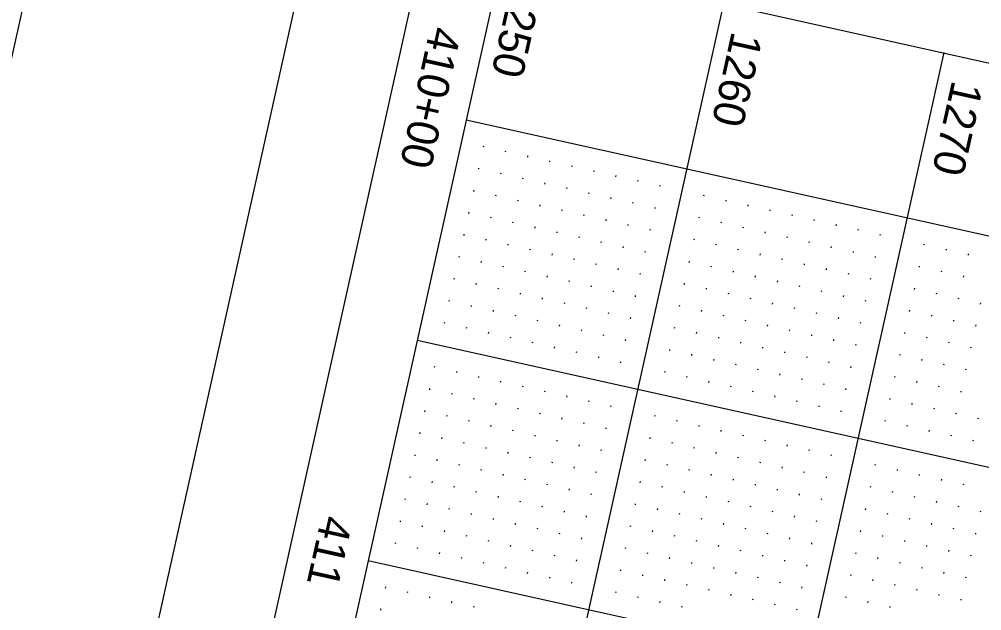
# Model space of a CAD drawing. Extents: x 2149268 to 2150830, y 142155 to 144285.
# Drawn here: x 2149611.6 to 2149824.8, y 143829.9 to 143960.9 of the extents above; entities that cross this region are included whole.
import ezdxf

# ---------------------------------------------------------------- set-up
doc = ezdxf.new("R2010")
doc.units = 0
for name, color, linetype in [('SHT_Plan_Profile_Sheet_Elev_Txt', 7, 'Continuous'), ('SHT_Plan_Profile_Sheet_Sta_Txt', 7, 'Continuous'), ('SHT_Plot_Shape_Full', 7, 'Continuous'), ('SHT_Plot_Shape_Half', 7, 'Continuous'), ('SHT_Profile_Grid_Major', 7, 'Continuous'), ('SHT_Profile_Grid_Minor', 7, 'Continuous'), ('SHT_Sheet_Border', 7, 'Continuous')]:
    doc.layers.add(name, color=color, linetype=linetype)

msp = doc.modelspace()

# ---------------------------------------------------------------- linework, layer by layer
at = {"layer": 'SHT_Plot_Shape_Full'}
msp.add_lwpolyline([(2150830.28, 143911.83), (2150439.58, 142154.75), (2149268.19, 142415.21), (2149658.89, 144172.3)], close=True, dxfattribs=at)
at = {"layer": 'SHT_Plot_Shape_Half'}
msp.add_lwpolyline([(2150772.24, 143840.86), (2150403.25, 142181.39), (2149329.47, 142420.15), (2149698.47, 144079.62)], close=True, dxfattribs=at)
at = {"layer": 'SHT_Profile_Grid_Major'}
for p, q in [((2149767.6, 143964.37), (2149425.74, 142426.92)), ((2149816.41, 143953.52), (2149474.54, 142416.07)), ((2149699.8, 143889.81), (2150187.88, 143781.28)), ((2149688.94, 143841), (2150177.02, 143732.47))]:
    msp.add_line(p, q, dxfattribs=at)
at = {"layer": 'SHT_Profile_Grid_Minor'}
for p, q in [((2149714.47, 143932.77), (2149714.42, 143932.53)), ((2149719.35, 143931.69), (2149719.3, 143931.44)), ((2149724.23, 143930.6), (2149724.18, 143930.36)), ((2149729.12, 143929.52), (2149729.06, 143929.27)), ((2149713.39, 143927.89), (2149713.33, 143927.65)), ((2149718.27, 143926.81), (2149718.21, 143926.56)), ((2149734, 143928.43), (2149733.94, 143928.19)), ((2149738.88, 143927.35), (2149738.82, 143927.1)), ((2149723.15, 143925.72), (2149723.1, 143925.48)), ((2149728.03, 143924.64), (2149727.98, 143924.39)), ((2149743.76, 143926.26), (2149743.7, 143926.02)), ((2149748.64, 143925.18), (2149748.58, 143924.93)), ((2149712.3, 143923.01), (2149712.25, 143922.77)), ((2149732.91, 143923.55), (2149732.86, 143923.31)), ((2149737.79, 143922.47), (2149737.74, 143922.22)), ((2149753.52, 143924.09), (2149753.47, 143923.85)), ((2149717.18, 143921.93), (2149717.13, 143921.68)), ((2149722.06, 143920.84), (2149722.01, 143920.6)), ((2149742.67, 143921.38), (2149742.62, 143921.14)), ((2149747.55, 143920.3), (2149747.5, 143920.05)), ((2149763.28, 143921.92), (2149763.23, 143921.68)), ((2149768.16, 143920.84), (2149768.11, 143920.59)), ((2149711.22, 143918.13), (2149711.16, 143917.89)), ((2149726.95, 143919.76), (2149726.89, 143919.51)), ((2149731.83, 143918.67), (2149731.77, 143918.43)), ((2149752.43, 143919.21), (2149752.38, 143918.97)), ((2149773.04, 143919.75), (2149772.99, 143919.51)), ((2149777.92, 143918.66), (2149777.87, 143918.42)), ((2149716.1, 143917.05), (2149716.04, 143916.8)), ((2149720.98, 143915.96), (2149720.92, 143915.72)), ((2149736.71, 143917.59), (2149736.65, 143917.34)), ((2149741.59, 143916.5), (2149741.53, 143916.26)), ((2149762.2, 143917.04), (2149762.14, 143916.8)), ((2149767.08, 143915.95), (2149767.02, 143915.71)), ((2149782.8, 143917.58), (2149782.75, 143917.34)), ((2149787.69, 143916.49), (2149787.63, 143916.25)), ((2149725.86, 143914.88), (2149725.81, 143914.63)), ((2149730.74, 143913.79), (2149730.69, 143913.55)), ((2149746.47, 143915.41), (2149746.41, 143915.17)), ((2149751.35, 143914.33), (2149751.29, 143914.09)), ((2149771.96, 143914.87), (2149771.9, 143914.63)), ((2149776.84, 143913.78), (2149776.78, 143913.54)), ((2149792.57, 143915.41), (2149792.51, 143915.16)), ((2149797.45, 143914.32), (2149797.39, 143914.08)), ((2149710.13, 143913.25), (2149710.08, 143913.01)), ((2149715.01, 143912.17), (2149714.96, 143911.92)), ((2149735.62, 143912.7), (2149735.57, 143912.46)), ((2149740.5, 143911.62), (2149740.45, 143911.38)), ((2149761.11, 143912.16), (2149761.06, 143911.92)), ((2149781.72, 143912.7), (2149781.66, 143912.45)), ((2149786.6, 143911.61), (2149786.55, 143911.37)), ((2149802.33, 143913.24), (2149802.27, 143912.99)), ((2149719.89, 143911.08), (2149719.84, 143910.84)), ((2149724.77, 143909.99), (2149724.72, 143909.75)), ((2149745.38, 143910.53), (2149745.33, 143910.29)), ((2149750.26, 143909.45), (2149750.21, 143909.2)), ((2149765.99, 143911.07), (2149765.94, 143910.83)), ((2149770.87, 143909.99), (2149770.82, 143909.74)), ((2149791.48, 143910.53), (2149791.43, 143910.28)), ((2149812.09, 143911.07), (2149812.03, 143910.82)), ((2149816.97, 143909.98), (2149816.92, 143909.74)), ((2149709.05, 143908.37), (2149708.99, 143908.13)), ((2149729.66, 143908.91), (2149729.6, 143908.67)), ((2149734.54, 143907.82), (2149734.48, 143907.58)), ((2149775.75, 143908.9), (2149775.7, 143908.66)), ((2149780.63, 143907.82), (2149780.58, 143907.57)), ((2149796.36, 143909.44), (2149796.31, 143909.2)), ((2149801.24, 143908.36), (2149801.19, 143908.11)), ((2149821.85, 143908.9), (2149821.8, 143908.65)), ((2149713.93, 143907.28), (2149713.87, 143907.04)), ((2149718.81, 143906.2), (2149718.75, 143905.95)), ((2149739.42, 143906.74), (2149739.36, 143906.49)), ((2149744.3, 143905.65), (2149744.24, 143905.41)), ((2149760.03, 143907.28), (2149759.97, 143907.03)), ((2149764.91, 143906.19), (2149764.85, 143905.95)), ((2149785.51, 143906.73), (2149785.46, 143906.49)), ((2149790.4, 143905.65), (2149790.34, 143905.4)), ((2149811, 143906.19), (2149810.95, 143905.94)), ((2149707.96, 143903.49), (2149707.91, 143903.24)), ((2149723.69, 143905.11), (2149723.63, 143904.87)), ((2149728.57, 143904.03), (2149728.52, 143903.78)), ((2149749.18, 143904.57), (2149749.12, 143904.32)), ((2149769.79, 143905.11), (2149769.73, 143904.86)), ((2149774.67, 143904.02), (2149774.61, 143903.78)), ((2149795.28, 143904.56), (2149795.22, 143904.32)), ((2149800.16, 143903.48), (2149800.1, 143903.23)), ((2149815.88, 143905.1), (2149815.83, 143904.86)), ((2149820.77, 143904.02), (2149820.71, 143903.77)), ((2149712.84, 143902.4), (2149712.79, 143902.16)), ((2149717.72, 143901.32), (2149717.67, 143901.07)), ((2149733.45, 143902.94), (2149733.4, 143902.7)), ((2149738.33, 143901.86), (2149738.28, 143901.61)), ((2149758.94, 143902.4), (2149758.89, 143902.15)), ((2149763.82, 143901.31), (2149763.77, 143901.07)), ((2149779.55, 143902.94), (2149779.49, 143902.69)), ((2149784.43, 143901.85), (2149784.38, 143901.61)), ((2149809.92, 143901.31), (2149809.86, 143901.06)), ((2149722.6, 143900.23), (2149722.55, 143899.99)), ((2149727.48, 143899.15), (2149727.43, 143898.9)), ((2149743.21, 143900.77), (2149743.16, 143900.53)), ((2149748.09, 143899.69), (2149748.04, 143899.44)), ((2149768.7, 143900.23), (2149768.65, 143899.98)), ((2149773.58, 143899.14), (2149773.53, 143898.9)), ((2149789.31, 143900.77), (2149789.26, 143900.52)), ((2149794.19, 143899.68), (2149794.14, 143899.44)), ((2149814.8, 143900.22), (2149814.75, 143899.98)), ((2149819.68, 143899.14), (2149819.63, 143898.89)), ((2149706.88, 143898.61), (2149706.82, 143898.36)), ((2149711.76, 143897.52), (2149711.7, 143897.28)), ((2149732.37, 143898.06), (2149732.31, 143897.82)), ((2149737.25, 143896.98), (2149737.19, 143896.73)), ((2149757.85, 143897.52), (2149757.8, 143897.27)), ((2149778.46, 143898.06), (2149778.41, 143897.81)), ((2149783.34, 143896.97), (2149783.29, 143896.73)), ((2149799.07, 143898.6), (2149799.02, 143898.35)), ((2149824.56, 143898.05), (2149824.51, 143897.81)), ((2149716.64, 143896.44), (2149716.58, 143896.19)), ((2149721.52, 143895.35), (2149721.46, 143895.11)), ((2149742.13, 143895.89), (2149742.07, 143895.65)), ((2149747.01, 143894.81), (2149746.95, 143894.56)), ((2149762.74, 143896.43), (2149762.68, 143896.19)), ((2149767.62, 143895.35), (2149767.56, 143895.1)), ((2149788.22, 143895.89), (2149788.17, 143895.64)), ((2149793.11, 143894.8), (2149793.05, 143894.56)), ((2149808.83, 143896.43), (2149808.78, 143896.18)), ((2149813.71, 143895.34), (2149813.66, 143895.1)), ((2149705.79, 143893.73), (2149705.74, 143893.48)), ((2149710.67, 143892.64), (2149710.62, 143892.4)), ((2149726.4, 143894.27), (2149726.35, 143894.02)), ((2149731.28, 143893.18), (2149731.23, 143892.94)), ((2149756.77, 143892.64), (2149756.72, 143892.39)), ((2149772.5, 143894.26), (2149772.44, 143894.02)), ((2149777.38, 143893.18), (2149777.32, 143892.93)), ((2149797.99, 143893.72), (2149797.93, 143893.47)), ((2149818.59, 143894.25), (2149818.54, 143894.01)), ((2149823.48, 143893.17), (2149823.42, 143892.93)), ((2149715.55, 143891.56), (2149715.5, 143891.31)), ((2149720.43, 143890.47), (2149720.38, 143890.23)), ((2149736.16, 143892.1), (2149736.11, 143891.85)), ((2149741.04, 143891.01), (2149740.99, 143890.77)), ((2149761.65, 143891.55), (2149761.6, 143891.31)), ((2149766.53, 143890.47), (2149766.48, 143890.22)), ((2149782.26, 143892.09), (2149782.2, 143891.85)), ((2149787.14, 143891.01), (2149787.09, 143890.76)), ((2149807.75, 143891.54), (2149807.69, 143891.3)), ((2149812.63, 143890.46), (2149812.57, 143890.22)), ((2149725.31, 143889.39), (2149725.26, 143889.14)), ((2149730.19, 143888.3), (2149730.14, 143888.06)), ((2149745.92, 143889.93), (2149745.87, 143889.68)), ((2149771.41, 143889.38), (2149771.36, 143889.14)), ((2149776.29, 143888.29), (2149776.24, 143888.05)), ((2149792.02, 143889.92), (2149791.97, 143889.68)), ((2149796.9, 143888.83), (2149796.85, 143888.59)), ((2149817.51, 143889.37), (2149817.46, 143889.13)), ((2149822.39, 143888.29), (2149822.34, 143888.04)), ((2149735.08, 143887.22), (2149735.02, 143886.97)), ((2149739.96, 143886.13), (2149739.9, 143885.89)), ((2149755.68, 143887.76), (2149755.63, 143887.51)), ((2149760.57, 143886.67), (2149760.51, 143886.43)), ((2149781.17, 143887.21), (2149781.12, 143886.97)), ((2149786.05, 143886.12), (2149786, 143885.88)), ((2149806.66, 143886.66), (2149806.61, 143886.42)), ((2149703.62, 143883.97), (2149703.57, 143883.72)), ((2149744.84, 143885.04), (2149744.78, 143884.8)), ((2149765.45, 143885.58), (2149765.39, 143885.34)), ((2149770.33, 143884.5), (2149770.27, 143884.26)), ((2149790.94, 143885.04), (2149790.88, 143884.79)), ((2149795.82, 143883.95), (2149795.76, 143883.71)), ((2149811.54, 143885.58), (2149811.49, 143885.33)), ((2149816.42, 143884.49), (2149816.37, 143884.25)), ((2149708.5, 143882.88), (2149708.45, 143882.64)), ((2149713.38, 143881.79), (2149713.33, 143881.55)), ((2149754.6, 143882.87), (2149754.54, 143882.63)), ((2149759.48, 143881.79), (2149759.43, 143881.55)), ((2149775.21, 143883.41), (2149775.15, 143883.17)), ((2149780.09, 143882.33), (2149780.03, 143882.08)), ((2149805.58, 143881.78), (2149805.52, 143881.54)), ((2149821.31, 143883.41), (2149821.25, 143883.16)), ((2149718.26, 143880.71), (2149718.21, 143880.47)), ((2149723.14, 143879.62), (2149723.09, 143879.38)), ((2149764.36, 143880.7), (2149764.31, 143880.46)), ((2149769.24, 143879.62), (2149769.19, 143879.37)), ((2149784.97, 143881.24), (2149784.91, 143881)), ((2149789.85, 143880.16), (2149789.8, 143879.91)), ((2149810.46, 143880.7), (2149810.4, 143880.45)), ((2149815.34, 143879.61), (2149815.28, 143879.37)), ((2149702.54, 143879.08), (2149702.48, 143878.84)), ((2149707.42, 143878), (2149707.36, 143877.76)), ((2149728.02, 143878.54), (2149727.97, 143878.3)), ((2149774.12, 143878.53), (2149774.07, 143878.29)), ((2149794.73, 143879.07), (2149794.68, 143878.83)), ((2149820.22, 143878.53), (2149820.17, 143878.28)), ((2149712.3, 143876.91), (2149712.24, 143876.67)), ((2149717.18, 143875.83), (2149717.12, 143875.58)), ((2149732.91, 143877.45), (2149732.85, 143877.21)), ((2149737.79, 143876.37), (2149737.73, 143876.12)), ((2149779, 143877.45), (2149778.95, 143877.2)), ((2149783.88, 143876.36), (2149783.83, 143876.12)), ((2149804.49, 143876.9), (2149804.44, 143876.66)), ((2149809.37, 143875.82), (2149809.32, 143875.57)), ((2149701.45, 143874.2), (2149701.4, 143873.96)), ((2149722.06, 143874.74), (2149722, 143874.5)), ((2149726.94, 143873.66), (2149726.88, 143873.41)), ((2149742.67, 143875.28), (2149742.61, 143875.04)), ((2149788.76, 143875.28), (2149788.71, 143875.03)), ((2149793.65, 143874.19), (2149793.59, 143873.95)), ((2149814.25, 143874.73), (2149814.2, 143874.49)), ((2149819.13, 143873.65), (2149819.08, 143873.4)), ((2149706.33, 143873.12), (2149706.28, 143872.87)), ((2149711.21, 143872.03), (2149711.16, 143871.79)), ((2149731.82, 143872.57), (2149731.77, 143872.33)), ((2149736.7, 143871.49), (2149736.65, 143871.24)), ((2149752.43, 143873.11), (2149752.37, 143872.87)), ((2149757.31, 143872.03), (2149757.25, 143871.78)), ((2149803.41, 143872.02), (2149803.35, 143871.78)), ((2149824.02, 143872.56), (2149823.96, 143872.32)), ((2149700.36, 143869.32), (2149700.31, 143869.08)), ((2149716.09, 143870.95), (2149716.04, 143870.7)), ((2149720.97, 143869.86), (2149720.92, 143869.62)), ((2149741.58, 143870.4), (2149741.53, 143870.16)), ((2149762.19, 143870.94), (2149762.14, 143870.7)), ((2149767.07, 143869.86), (2149767.02, 143869.61)), ((2149808.29, 143870.94), (2149808.23, 143870.69)), ((2149813.17, 143869.85), (2149813.11, 143869.61)), ((2149705.25, 143868.24), (2149705.19, 143867.99)), ((2149710.13, 143867.15), (2149710.07, 143866.91)), ((2149725.85, 143868.78), (2149725.8, 143868.53)), ((2149730.73, 143867.69), (2149730.68, 143867.45)), ((2149751.34, 143868.23), (2149751.29, 143867.99)), ((2149756.22, 143867.15), (2149756.17, 143866.9)), ((2149771.95, 143868.77), (2149771.9, 143868.53)), ((2149776.83, 143867.69), (2149776.78, 143867.44)), ((2149818.05, 143868.77), (2149818, 143868.52)), ((2149822.93, 143867.68), (2149822.88, 143867.44)), ((2149715.01, 143866.07), (2149714.95, 143865.82)), ((2149719.89, 143864.98), (2149719.83, 143864.74)), ((2149735.62, 143866.61), (2149735.56, 143866.36)), ((2149740.5, 143865.52), (2149740.44, 143865.28)), ((2149761.1, 143866.06), (2149761.05, 143865.82)), ((2149765.99, 143864.98), (2149765.93, 143864.73)), ((2149781.71, 143866.6), (2149781.66, 143866.36)), ((2149786.59, 143865.52), (2149786.54, 143865.27)), ((2149699.28, 143864.44), (2149699.23, 143864.2)), ((2149704.16, 143863.36), (2149704.11, 143863.11)), ((2149724.77, 143863.9), (2149724.71, 143863.65)), ((2149729.65, 143862.81), (2149729.6, 143862.57)), ((2149750.26, 143863.35), (2149750.2, 143863.11)), ((2149770.87, 143863.89), (2149770.81, 143863.65)), ((2149775.75, 143862.81), (2149775.69, 143862.56)), ((2149791.47, 143864.43), (2149791.42, 143864.19)), ((2149709.04, 143862.27), (2149708.99, 143862.03)), ((2149713.92, 143861.19), (2149713.87, 143860.94)), ((2149734.53, 143861.73), (2149734.48, 143861.48)), ((2149739.41, 143860.64), (2149739.36, 143860.4)), ((2149755.14, 143862.27), (2149755.08, 143862.02)), ((2149760.02, 143861.18), (2149759.97, 143860.94)), ((2149780.63, 143861.72), (2149780.57, 143861.48)), ((2149785.51, 143860.63), (2149785.45, 143860.39)), ((2149801.24, 143862.26), (2149801.18, 143862.02)), ((2149806.12, 143861.17), (2149806.06, 143860.93)), ((2149698.19, 143859.56), (2149698.14, 143859.32)), ((2149703.07, 143858.48), (2149703.02, 143858.23)), ((2149718.8, 143860.1), (2149718.75, 143859.86)), ((2149723.68, 143859.02), (2149723.63, 143858.77)), ((2149749.17, 143858.47), (2149749.12, 143858.23)), ((2149764.9, 143860.1), (2149764.85, 143859.85)), ((2149769.78, 143859.01), (2149769.73, 143858.77)), ((2149790.39, 143859.55), (2149790.34, 143859.31)), ((2149811, 143860.09), (2149810.94, 143859.85)), ((2149815.88, 143859), (2149815.82, 143858.76)), ((2149707.96, 143857.39), (2149707.9, 143857.15)), ((2149712.84, 143856.31), (2149712.78, 143856.06)), ((2149728.56, 143857.93), (2149728.51, 143857.69)), ((2149733.44, 143856.85), (2149733.39, 143856.6)), ((2149754.05, 143857.39), (2149754, 143857.14)), ((2149758.93, 143856.3), (2149758.88, 143856.06)), ((2149774.66, 143857.92), (2149774.61, 143857.68)), ((2149779.54, 143856.84), (2149779.49, 143856.6)), ((2149800.15, 143857.38), (2149800.1, 143857.14)), ((2149805.03, 143856.29), (2149804.98, 143856.05)), ((2149820.76, 143857.92), (2149820.71, 143857.67)), ((2149697.11, 143854.68), (2149697.05, 143854.44)), ((2149717.72, 143855.22), (2149717.66, 143854.98)), ((2149722.6, 143854.14), (2149722.54, 143853.89)), ((2149738.33, 143855.76), (2149738.27, 143855.52)), ((2149763.81, 143855.21), (2149763.76, 143854.97)), ((2149768.7, 143854.13), (2149768.64, 143853.89)), ((2149784.42, 143855.75), (2149784.37, 143855.51)), ((2149789.3, 143854.67), (2149789.25, 143854.42)), ((2149809.91, 143855.21), (2149809.86, 143854.96)), ((2149814.79, 143854.12), (2149814.74, 143853.88)), ((2149701.99, 143853.6), (2149701.94, 143853.35)), ((2149706.87, 143852.51), (2149706.82, 143852.27)), ((2149727.48, 143853.05), (2149727.42, 143852.81)), ((2149732.36, 143851.96), (2149732.31, 143851.72)), ((2149748.09, 143853.59), (2149748.03, 143853.35)), ((2149752.97, 143852.5), (2149752.91, 143852.26)), ((2149773.58, 143853.04), (2149773.52, 143852.8)), ((2149778.46, 143851.96), (2149778.4, 143851.71)), ((2149799.07, 143852.5), (2149799.01, 143852.25)), ((2149819.67, 143853.04), (2149819.62, 143852.79)), ((2149824.55, 143851.95), (2149824.5, 143851.71)), ((2149696.02, 143849.8), (2149695.97, 143849.56)), ((2149711.75, 143851.42), (2149711.7, 143851.18)), ((2149716.63, 143850.34), (2149716.58, 143850.1)), ((2149737.24, 143850.88), (2149737.19, 143850.64)), ((2149757.85, 143851.42), (2149757.79, 143851.17)), ((2149762.73, 143850.33), (2149762.68, 143850.09)), ((2149783.34, 143850.87), (2149783.28, 143850.63)), ((2149788.22, 143849.79), (2149788.16, 143849.54)), ((2149803.95, 143851.41), (2149803.89, 143851.17)), ((2149808.83, 143850.33), (2149808.77, 143850.08)), ((2149700.9, 143848.71), (2149700.85, 143848.47)), ((2149705.79, 143847.63), (2149705.73, 143847.39)), ((2149721.51, 143849.25), (2149721.46, 143849.01)), ((2149726.39, 143848.17), (2149726.34, 143847.93)), ((2149747, 143848.71), (2149746.95, 143848.46)), ((2149751.88, 143847.62), (2149751.83, 143847.38)), ((2149767.61, 143849.25), (2149767.56, 143849)), ((2149772.49, 143848.16), (2149772.44, 143847.92)), ((2149813.71, 143849.24), (2149813.65, 143849)), ((2149818.59, 143848.16), (2149818.53, 143847.91)), ((2149710.67, 143846.54), (2149710.61, 143846.3)), ((2149731.27, 143847.08), (2149731.22, 143846.84)), ((2149736.16, 143846), (2149736.1, 143845.75)), ((2149756.76, 143846.54), (2149756.71, 143846.29)), ((2149777.37, 143847.08), (2149777.32, 143846.83)), ((2149782.25, 143845.99), (2149782.2, 143845.75)), ((2149797.98, 143847.62), (2149797.93, 143847.37)), ((2149802.86, 143846.53), (2149802.81, 143846.29)), ((2149823.47, 143847.07), (2149823.42, 143846.83)), ((2149694.94, 143844.92), (2149694.88, 143844.68)), ((2149699.82, 143843.83), (2149699.76, 143843.59)), ((2149715.55, 143845.46), (2149715.49, 143845.21)), ((2149720.43, 143844.37), (2149720.37, 143844.13)), ((2149745.92, 143843.83), (2149745.86, 143843.58)), ((2149761.64, 143845.45), (2149761.59, 143845.21)), ((2149766.53, 143844.37), (2149766.47, 143844.12)), ((2149787.13, 143844.91), (2149787.08, 143844.66)), ((2149807.74, 143845.45), (2149807.69, 143845.2)), ((2149812.62, 143844.36), (2149812.57, 143844.12)), ((2149704.7, 143842.75), (2149704.65, 143842.5)), ((2149709.58, 143841.66), (2149709.53, 143841.42)), ((2149725.31, 143843.29), (2149725.25, 143843.04)), ((2149730.19, 143842.2), (2149730.13, 143841.96)), ((2149750.8, 143842.74), (2149750.74, 143842.5)), ((2149755.68, 143841.66), (2149755.62, 143841.41)), ((2149771.41, 143843.28), (2149771.35, 143843.04)), ((2149776.29, 143842.2), (2149776.23, 143841.95)), ((2149796.9, 143842.74), (2149796.84, 143842.49)), ((2149801.78, 143841.65), (2149801.72, 143841.41)), ((2149817.5, 143843.28), (2149817.45, 143843.03)), ((2149822.38, 143842.19), (2149822.33, 143841.95)), ((2149714.46, 143840.58), (2149714.41, 143840.33)), ((2149719.34, 143839.49), (2149719.29, 143839.25)), ((2149735.07, 143841.12), (2149735.02, 143840.87)), ((2149760.56, 143840.57), (2149760.5, 143840.33)), ((2149765.44, 143839.49), (2149765.39, 143839.24)), ((2149781.17, 143841.11), (2149781.11, 143840.87)), ((2149786.05, 143840.03), (2149785.99, 143839.78)), ((2149806.66, 143840.57), (2149806.6, 143840.32)), ((2149811.54, 143839.48), (2149811.48, 143839.24)), ((2149724.22, 143838.41), (2149724.17, 143838.16)), ((2149729.1, 143837.32), (2149729.05, 143837.08)), ((2149744.83, 143838.95), (2149744.78, 143838.7)), ((2149749.71, 143837.86), (2149749.66, 143837.62)), ((2149770.32, 143838.4), (2149770.27, 143838.16)), ((2149775.2, 143837.32), (2149775.15, 143837.07)), ((2149795.81, 143837.86), (2149795.76, 143837.61)), ((2149816.42, 143838.4), (2149816.36, 143838.15)), ((2149821.3, 143837.31), (2149821.24, 143837.07)), ((2149692.77, 143835.16), (2149692.71, 143834.91)), ((2149733.98, 143836.24), (2149733.93, 143835.99)), ((2149754.59, 143836.78), (2149754.54, 143836.53)), ((2149759.47, 143835.69), (2149759.42, 143835.45)), ((2149780.08, 143836.23), (2149780.03, 143835.99)), ((2149784.96, 143835.15), (2149784.91, 143834.9)), ((2149800.69, 143836.77), (2149800.64, 143836.53)), ((2149805.57, 143835.69), (2149805.52, 143835.44)), ((2149697.65, 143834.07), (2149697.59, 143833.83)), ((2149702.53, 143832.99), (2149702.47, 143832.74)), ((2149743.75, 143834.07), (2149743.69, 143833.82)), ((2149748.63, 143832.98), (2149748.57, 143832.74)), ((2149764.35, 143834.61), (2149764.3, 143834.36)), ((2149769.24, 143833.52), (2149769.18, 143833.28)), ((2149794.72, 143832.98), (2149794.67, 143832.73)), ((2149810.45, 143834.6), (2149810.4, 143834.36)), ((2149815.33, 143833.51), (2149815.28, 143833.27)), ((2149707.41, 143831.9), (2149707.36, 143831.66)), ((2149712.29, 143830.82), (2149712.24, 143830.57)), ((2149753.51, 143831.9), (2149753.45, 143831.65)), ((2149758.39, 143830.81), (2149758.33, 143830.57)), ((2149774.12, 143832.44), (2149774.06, 143832.19)), ((2149779, 143831.35), (2149778.94, 143831.11)), ((2149799.61, 143831.89), (2149799.55, 143831.65)), ((2149804.49, 143830.8), (2149804.43, 143830.56)), ((2149820.21, 143832.43), (2149820.16, 143832.19)), ((2149691.68, 143830.28), (2149691.63, 143830.03)), ((2149783.88, 143830.26), (2149783.82, 143830.02))]:
    msp.add_line(p, q, dxfattribs=at)
at = {"layer": 'SHT_Sheet_Border'}
for p, q in [((2149718.79, 143975.22), (2149433.9, 142694.01)), ((2149710.65, 143938.62), (2150198.73, 143830.09))]:
    msp.add_line(p, q, dxfattribs=at)
msp.add_lwpolyline([(2150726.67, 143751.11), (2150384.81, 142213.66), (2149359.84, 142441.57), (2149701.71, 143979.02)], close=True, dxfattribs=at)

# ---------------------------------------------------------------- texts
at = {"layer": 'SHT_Plan_Profile_Sheet_Elev_Txt'}
for s, p in [('1250', (2149720.7, 143969.27)), ('1260', (2149769.51, 143958.42)), ('1270', (2149818.32, 143947.57))]:
    msp.add_text(s, height=7, rotation=257.4638, dxfattribs=at).set_placement(p)
at = {"layer": 'SHT_Plan_Profile_Sheet_Sta_Txt'}
for s, p in [('410+00', (2149702.76, 143959.59)), ('411', (2149678.68, 143851.29))]:
    msp.add_text(s, height=7, rotation=257.4638, dxfattribs=at).set_placement(p)

doc.saveas('drawing.dxf')
